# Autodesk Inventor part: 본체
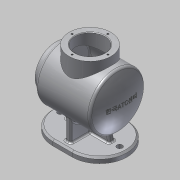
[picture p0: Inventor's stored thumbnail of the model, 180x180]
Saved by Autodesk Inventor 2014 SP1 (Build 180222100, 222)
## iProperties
Created: 2016-04
Part Number: 본체
Material: 알루미늄 6061
Document SubType Name: Modeling
Designer: SCD-A17
Density: 2.71 g/cm^3
Appearance: 알루미늄 - 평지
Mass: 913.842 g
Surface Area: 1223.62 cm^2
Volume: 337.211 cm^3
Author: SCD-A17
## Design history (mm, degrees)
sketch "스케치2"
  geometry: L1 (0, 0)-(122, 0); L2 (0, 0)-(0, 38); L3 (0, 38)-(12, 38); L4 (12, 38)-(12, 50); L5 (12, 50)-(111.087, 50); A1 r 120 centre (2, 0) between (122, 0) and (111.087, 50)
  constraints: 10 end point, 2 parallel, 2 perpendicular, 2 point on circle, 1 centre point, 1 horizontal, 1 point on line
  dimensions: "d0" = 122 distance of L1.start L1.end; "d1" = 12 distance of L2.end L3.end; "d2" = 76 diameter of L2.end L1; "d3" = 100 diameter of L4.end L1; "d4" = 240 diameter of A1
revolve "회전1" sketch "스케치2" stored, may be unused: angle "d5" = 90 deg
fillet "모깎기2" dims "d30" = 5
feature "쉘1" dims "d6" = 3
sketch "스케치3"
  geometry: C1 r 35 at (0, 0) reference; C2 r 38 at (0, 0) reference; C3 r 27 at (0, 0)
  constraints: 1 centre point, 1 coincident
  dimensions: "d7" = 54 diameter of C3
extrude "돌출1" join sketch "스케치3" distance "d8" = 15; taper "d9" = 0 deg
sketch "스케치4"
  geometry: L1 (0, -38)-(0, 38) reference; L2 (-5.5, -69)-(129.5, -69); L3 (129.5, -69)-(129.5, -79); L4 (129.5, -79)-(-5.5, -79); L5 (-5.5, -79)-(-5.5, -69); L6 (0, 0)-(122, 0); L7 (12, -45)-(12, 45) reference; L8 (17, 50)-(107.83, 50) reference; L9 (17, -50)-(107.83, -50) reference; L10 (62, 50)-(62, -50); A1 r 120 centre (2, 0) between (111.087, -50) and (111.087, 50) reference; 1 further point
  constraints: 12 end point, 2 parallel, 2 perpendicular, 2 point on line, 1 horizontal, 1 midpoint, 1 point on circle, 1 vertical alignment
  dimensions: "d10" = 79 distance from line of L4 L6.start; "d11" = 10 distance of L4.end L2.start; "d12" = 135 distance of L3.end L4.end; "d112" = 50 distance between parallel lines of L10 L7
extrude "돌출2" join sketch "스케치4" stored distance "d13" = 100; taper "d14" = 0 deg
fillet "모깎기1" dims "d15" = 50
node "작업 평면1"
sketch "스케치5"
  geometry: L1 (35, 100)-(0, 100) reference; L2 (0, 0)-(35, 0) reference; L3 (-44.5, 12)-(-44.5, 88) reference; L4 (-32.5, 5)-(-32.5, 95) reference; C1 r 38 at (17.5, 50); A1 r 50 centre (0, 50) between (0, 100) and (0, 0) reference; A2 r 50 centre (35, 50) between (35, 0) and (35, 100) reference; 1 further point
  constraints: 1 centre point, 1 horizontal alignment, 1 midpoint
  dimensions: "d82" = 76 diameter of C1; "d84" = 50 distance from line of C1.centre L4
  node "투영된 루프1"
sketch "스케치7"
  geometry: L1 (0, 100)-(35, 100) reference; L2 (-22.5, 55)-(57.5, 55); L3 (57.5, 55)-(57.5, 45); L4 (57.5, 45)-(-22.5, 45); L5 (-22.5, 45)-(-22.5, 55); L6 (12.5, 90)-(22.5, 90); L7 (22.5, 90)-(22.5, 10); L8 (22.5, 10)-(12.5, 10); L9 (12.5, 10)-(12.5, 90); A1 r 50 centre (0, 50) between (0, 100) and (0, 0) reference; 7 further points
  constraints: 16 end point, 5 midpoint, 4 parallel, 2 horizontal, 2 horizontal alignment, 2 perpendicular, 2 vertical alignment, 1 point on circle
  dimensions: "d31" = 10 distance of L6.start L6.end; "d32" = 80 distance of L6.end L7.end; "d33" = 10 distance of L4.end L2.start; "d34" = 80 distance of L3.end L4.end
extrude "돌출5" join sketch "스케치7" stored distance "d37" = 100; taper "d38" = 0 deg
fillet "모깎기3" dims "d39" = 3
extrude "돌출6" join sketch "스케치7" stored distance "d40" = 100; taper "d41" = 0 deg
feature "면 기울기1" dims angle "d42" = 10 deg
feature "면 기울기2" dims angle "d43" = 10 deg
fillet "모깎기4" dims "d44" = 3
fillet "모깎기5" dims "d45" = 3
fillet "모깎기6" dims "d46" = 3
chamfer "모따기1" distance "d47" = 1; stored, may be unused: second distance "d48" = 2, angle "d49" = 45 deg
chamfer "모따기2" distance "d50" = 3; stored, may be unused: second distance "d51" = 2, angle "d52" = 45 deg
sketch "스케치8" dims "d53" = 65
  geometry: C1 r 38 at (0, 0) reference; C2 r 28 at (0, 0) reference; 2 further points
  constraints: 2 vertical alignment, 1 coincident, 2 other
hole "구멍2" sketch "스케치8" at (0, 32.5) diameter "d54" = 3.242; stored, may be unused: countersink angle "d58" = 90 deg, drill point angle "d60" = 118 deg; dims "d55" = 8, "d56" = 4, "d57" = 2, "d59" = 10
node "작업 평면2"
sketch "스케치10"
  geometry: 2 further points
  constraints: 1 coincident, 1 other
feature "엠보싱1" sketch "스케치10" dims "d75" = 0.5, "d76" = 0
sketch "스케치11"
  geometry: L1 (35, 0)-(0, 0) reference; L2 (0, 94)-(35, 94) reference; L3 (-47, 47)-(82, 47); L4 (17.5, 94)-(17.5, 0); C1 r 5 at (-36.5, 47); C2 r 5 at (71.5, 47); A1 r 47 centre (0, 47) between (0, 94) and (0, 0) reference; A2 r 47 centre (35, 47) between (35, 0) and (35, 94) reference; 1 further point
  constraints: 4 end point, 2 centre point, 2 horizontal alignment, 2 midpoint, 2 point on circle, 1 equal radius
  dimensions: "d77" = 10 diameter of C1; "d78" = 54 distance from line of C1.centre L4; "d79" = 54 distance from line of C2.centre L4
extrude "돌출7" cut sketch "스케치11" stored distance "d80" = 100; taper "d81" = 0 deg
extrude "돌출8" join sketch "스케치5" stored distance "d85" = 100; taper "d86" = 0 deg
hole "구멍4" diameter "d89" = 54; stored, may be unused: countersink angle "d93" = 90 deg, drill point angle "d95" = 0 deg; dims "d90" = 54, "d91" = 4, "d92" = 2, "d94" = 10, "d96" = 10, "d97" = 10
chamfer "모따기3" distance "d98" = 1; stored, may be unused: second distance "d99" = 2, angle "d100" = 45 deg
sketch "스케치12" dims "d101" = 65
  geometry: C1 r 38 at (0, 0) reference; C2 r 28 at (0, 0) reference; 3 further points
  constraints: 2 vertical alignment, 1 coincident, 2 other
hole "구멍5" sketch "스케치12" at (0, 32.5) diameter "d102" = 3.242; stored, may be unused: countersink angle "d106" = 90 deg, drill point angle "d108" = 0 deg; dims "d103" = 8, "d104" = 4, "d105" = 2, "d107" = 10
node "솔리드1"
pattern_circular "원형 패턴1" dims angle "d62" = 360 deg
pattern_circular "원형 패턴3" dims angle "d110" = 360 deg
other parameters: "d16" = -144
